(* Logix 5000 project; controller Test vendor 1 type 14 code 92 rev 33.11; software revision 33.00; part 2 of 2 *)
(* tags used below, declared in another part *)
   S15C : Banner_S15C_MGN_v4;
   Port_Data : Banner_IOL_Port_v4;
   Port : DINT;
   Local_Control : DINT;
   Command_Being_Processed : BOOL;
   Index_Write_Inprocess : INT;
   Index_Write_Control : INT;
   Update_Archive : BOOL;
   Inprocess_Index : DINT;
   RRS_Index2 : SINT;
   RRS_Index1 : SINT;
   RRS_Index3 : SINT;
   WRS_Index2 : SINT;
   WRS_Index3 : SINT;
   WRS_Index4 : SINT;
   WR_Control : DINT;
(* Banner_S15C_MGN_Param_v4, continued *)

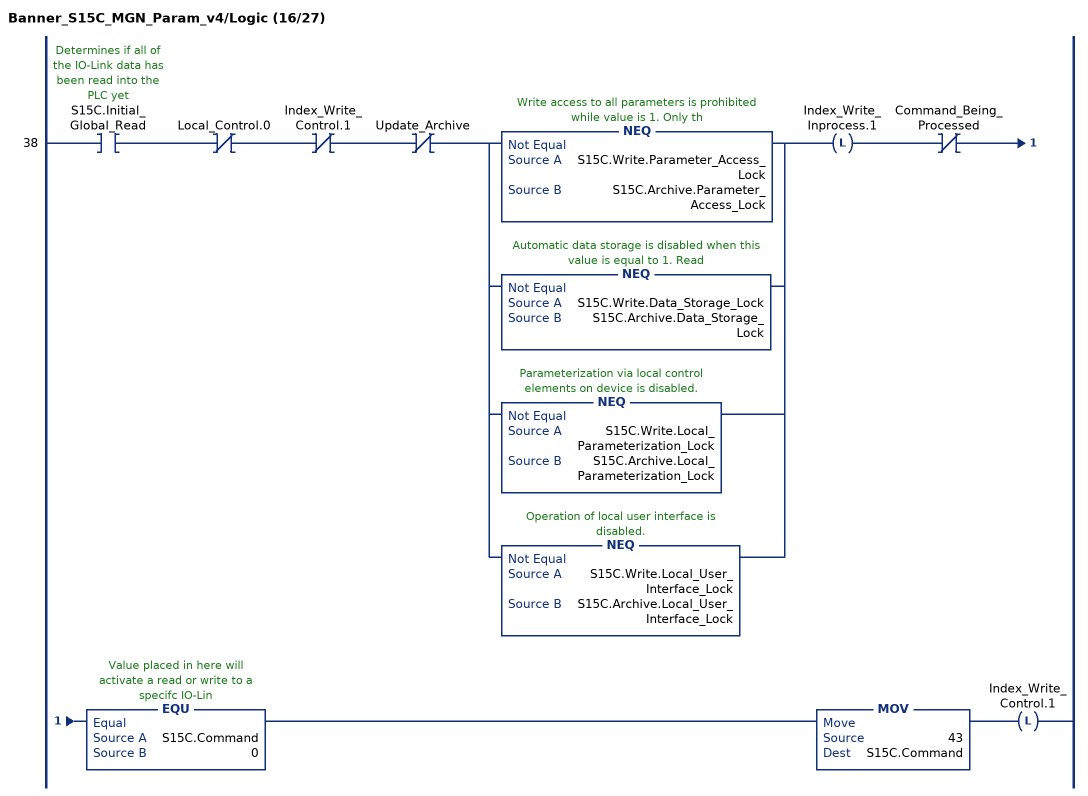
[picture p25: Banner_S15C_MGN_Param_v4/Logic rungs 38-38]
   38: XIC(S15C.Initial_Global_Read)XIO(Local_Control.0)XIO(Index_Write_Control.1)XIO(Update_Archive)[NEQ(S15C.Write.Parameter_Access_Lock,S15C.Archive.Parameter_Access_Lock) ,NEQ(S15C.Write.Data_Storage_Lock,S15C.Archive.Data_Storage_Lock) ,NEQ(S15C.Write.Local_Parameterization_Lock,S15C.Archive.Local_Parameterization_Lock) ,NEQ(S15C.Write.Local_User_Interface_Lock,S15C.Archive.Local_User_Interface_Lock) ]OTL(Index_Write_Inprocess.1)XIO(Command_Being_Processed)EQU(S15C.Command,0)MOV(43,S15C.Command)OTL(Index_Write_Control.1);
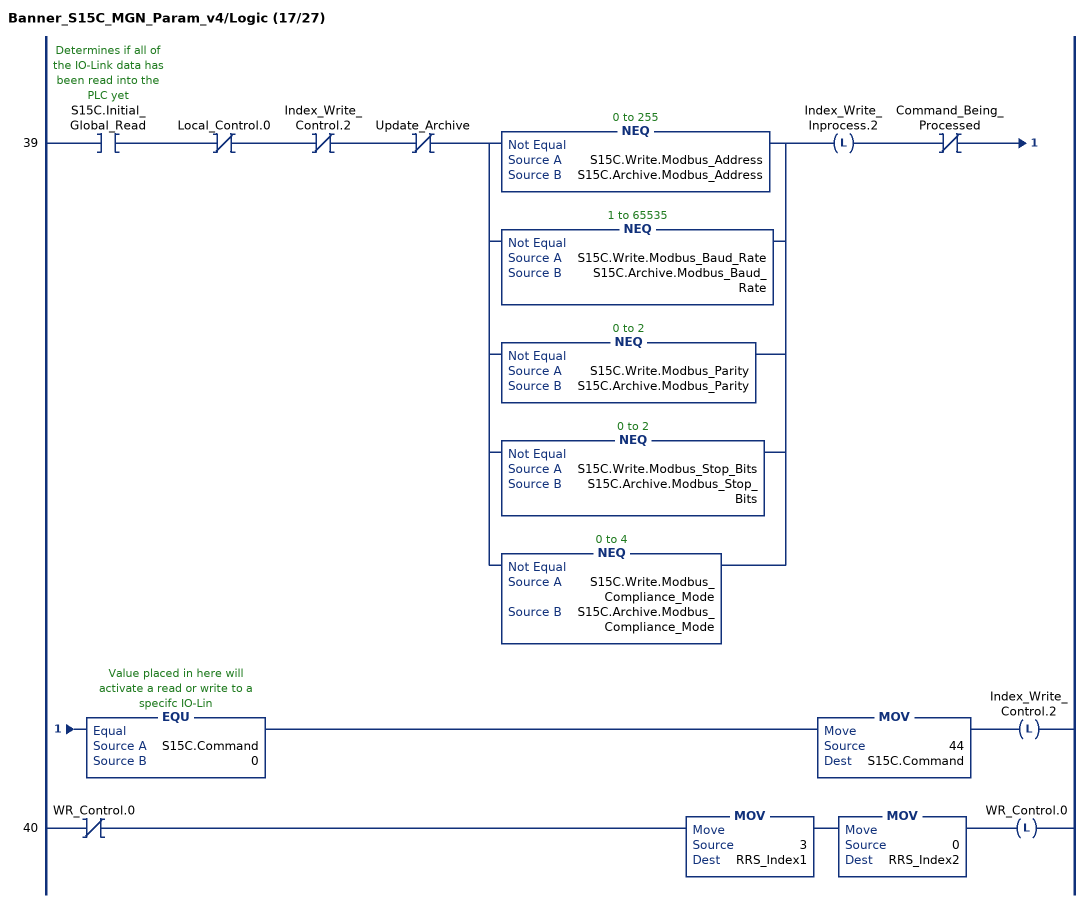
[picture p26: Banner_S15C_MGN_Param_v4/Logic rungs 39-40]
   39: XIC(S15C.Initial_Global_Read)XIO(Local_Control.0)XIO(Index_Write_Control.2)XIO(Update_Archive)[NEQ(S15C.Write.Modbus_Address,S15C.Archive.Modbus_Address) ,NEQ(S15C.Write.Modbus_Baud_Rate,S15C.Archive.Modbus_Baud_Rate) ,NEQ(S15C.Write.Modbus_Parity,S15C.Archive.Modbus_Parity) ,NEQ(S15C.Write.Modbus_Stop_Bits,S15C.Archive.Modbus_Stop_Bits) ,NEQ(S15C.Write.Modbus_Compliance_Mode,S15C.Archive.Modbus_Compliance_Mode) ]OTL(Index_Write_Inprocess.2)XIO(Command_Being_Processed)EQU(S15C.Command,0)MOV(44,S15C.Command)OTL(Index_Write_Control.2);
   40: XIO(WR_Control.0)MOV(3,RRS_Index1)MOV(0,RRS_Index2)OTL(WR_Control.0);
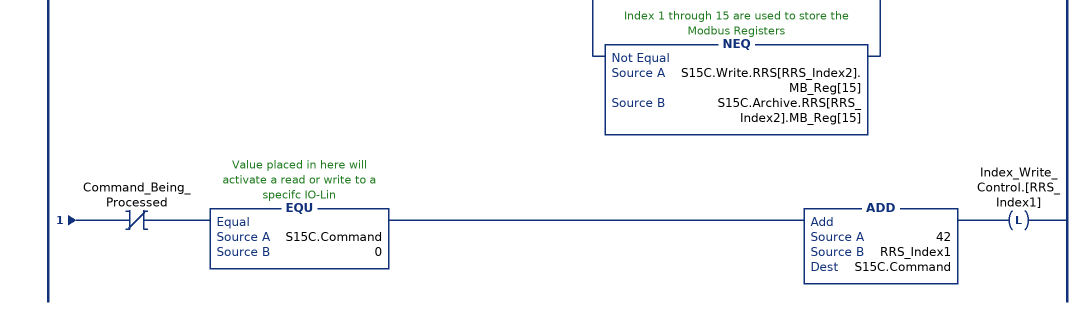
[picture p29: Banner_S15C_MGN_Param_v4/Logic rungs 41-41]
   41: XIC(S15C.Initial_Global_Read)XIC(WR_Control.0)XIO(Local_Control.0)XIO(Index_Write_Control.[RRS_Index1])XIO(Update_Archive)[NEQ(S15C.Write.RRS[RRS_Index2].MB_Reg[1],S15C.Archive.RRS[RRS_Index2].MB_Reg[1]) ,NEQ(S15C.Write.RRS[RRS_Index2].MB_Reg[2],S15C.Archive.RRS[RRS_Index2].MB_Reg[2]) ,NEQ(S15C.Write.RRS[RRS_Index2].MB_Reg[3],S15C.Archive.RRS[RRS_Index2].MB_Reg[3]) ,NEQ(S15C.Write.RRS[RRS_Index2].MB_Reg[4],S15C.Archive.RRS[RRS_Index2].MB_Reg[4]) ,NEQ(S15C.Write.RRS[RRS_Index2].MB_Reg[5],S15C.Archive.RRS[RRS_Index2].MB_Reg[5]) ,NEQ(S15C.Write.RRS[RRS_Index2].MB_Reg[6],S15C.Archive.RRS[RRS_Index2].MB_Reg[6]) ,NEQ(S15C.Write.RRS[RRS_Index2].MB_Reg[7],S15C.Archive.RRS[RRS_Index2].MB_Reg[7]) ,NEQ(S15C.Write.RRS[RRS_Index2].MB_Reg[8],S15C.Archive.RRS[RRS_Index2].MB_Reg[8]) ,NEQ(S15C.Write.RRS[RRS_Index2].MB_Reg[9],S15C.Archive.RRS[RRS_Index2].MB_Reg[9]) ,NEQ(S15C.Write.RRS[RRS_Index2].MB_Reg[10],S15C.Archive.RRS[RRS_Index2].MB_Reg[10]) ,NEQ(S15C.Write.RRS[RRS_Index2].MB_Reg[11],S15C.Archive.RRS[RRS_Index2].MB_Reg[11]) ,NEQ(S15C.Write.RRS[RRS_Index2].MB_Reg[12],S15C.Archive.RRS[RRS_Index2].MB_Reg[12]) ,NEQ(S15C.Write.RRS[RRS_Index2].MB_Reg[13],S15C.Archive.RRS[RRS_Index2].MB_Reg[13]) ,NEQ(S15C.Write.RRS[RRS_Index2].MB_Reg[14],S15C.Archive.RRS[RRS_Index2].MB_Reg[14]) ,NEQ(S15C.Write.RRS[RRS_Index2].MB_Reg[15],S15C.Archive.RRS[RRS_Index2].MB_Reg[15]) ]OTL(Index_Write_Inprocess.[RRS_Index1])XIO(Command_Being_Processed)EQU(S15C.Command,0)ADD(42,RRS_Index1,S15C.Command)OTL(Index_Write_Control.[RRS_Index1]);
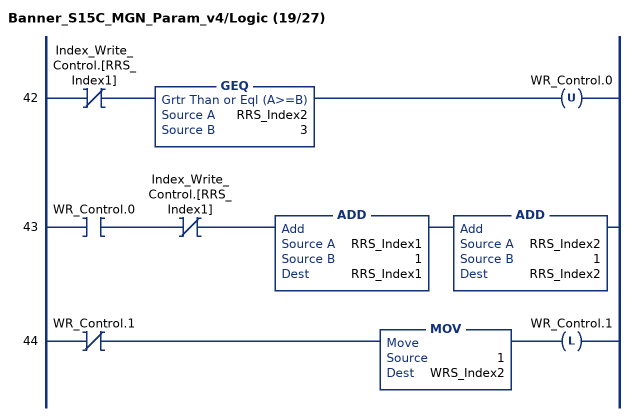
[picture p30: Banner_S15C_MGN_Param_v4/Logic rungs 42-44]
   42: XIO(Index_Write_Control.[RRS_Index1])GEQ(RRS_Index2,3)OTU(WR_Control.0);
   43: XIC(WR_Control.0)XIO(Index_Write_Control.[RRS_Index1])ADD(RRS_Index1,1,RRS_Index1)ADD(RRS_Index2,1,RRS_Index2);
   44: XIO(WR_Control.1)MOV(1,WRS_Index2)OTL(WR_Control.1);
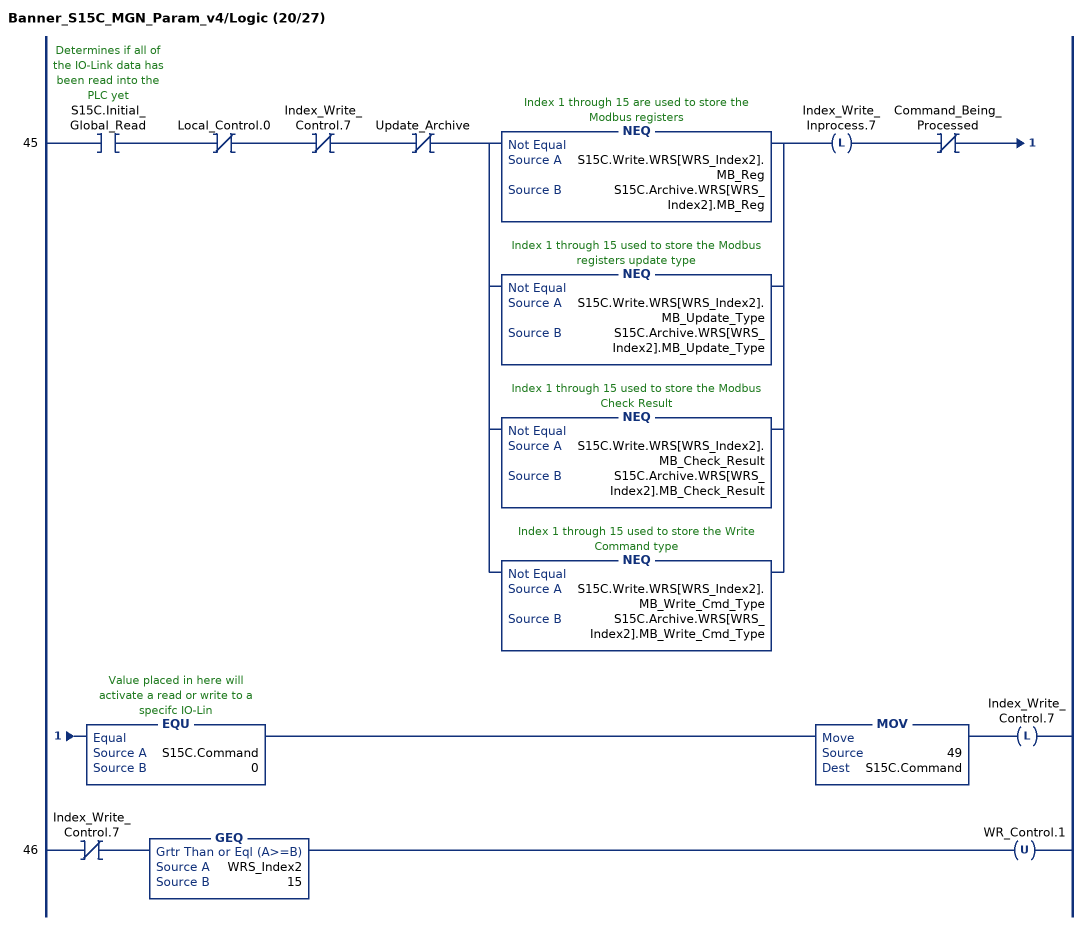
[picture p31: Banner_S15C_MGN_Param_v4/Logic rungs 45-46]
   45: XIC(S15C.Initial_Global_Read)XIO(Local_Control.0)XIO(Index_Write_Control.7)XIO(Update_Archive)[NEQ(S15C.Write.WRS[WRS_Index2].MB_Reg,S15C.Archive.WRS[WRS_Index2].MB_Reg) ,NEQ(S15C.Write.WRS[WRS_Index2].MB_Update_Type,S15C.Archive.WRS[WRS_Index2].MB_Update_Type) ,NEQ(S15C.Write.WRS[WRS_Index2].MB_Check_Result,S15C.Archive.WRS[WRS_Index2].MB_Check_Result) ,NEQ(S15C.Write.WRS[WRS_Index2].MB_Write_Cmd_Type,S15C.Archive.WRS[WRS_Index2].MB_Write_Cmd_Type) ]OTL(Index_Write_Inprocess.7)XIO(Command_Being_Processed)EQU(S15C.Command,0)MOV(49,S15C.Command)OTL(Index_Write_Control.7);
   46: XIO(Index_Write_Control.7)GEQ(WRS_Index2,15)OTU(WR_Control.1);
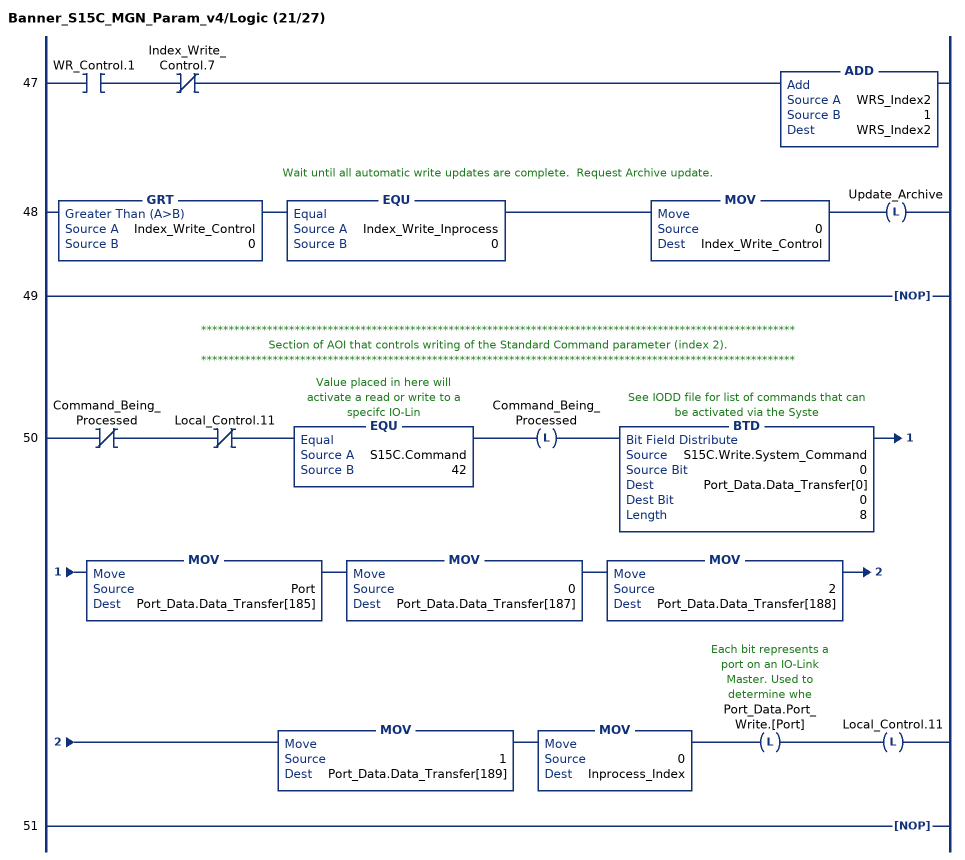
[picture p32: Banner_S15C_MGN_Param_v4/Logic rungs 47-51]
   47: XIC(WR_Control.1)XIO(Index_Write_Control.7)ADD(WRS_Index2,1,WRS_Index2);
   // Wait until all automatic write updates are complete.  Request Archive update.
   48: GRT(Index_Write_Control,0)EQU(Index_Write_Inprocess,0)MOV(0,Index_Write_Control)OTL(Update_Archive);
   49: NOP();
   // ************************************************************************************************************
   // Section of AOI that controls writing of the Standard Command parameter (index 2).
   // ************************************************************************************************************
   50: XIO(Command_Being_Processed)XIO(Local_Control.11)EQU(S15C.Command,42)OTL(Command_Being_Processed)BTD(S15C.Write.System_Command,0,Port_Data.Data_Transfer[0],0,8)MOV(Port,Port_Data.Data_Transfer[185])MOV(0,Port_Data.Data_Transfer[187])MOV(2,Port_Data.Data_Transfer[188])MOV(1,Port_Data.Data_Transfer[189])MOV(0,Inprocess_Index)OTL(Port_Data.Port_Write.[Port])OTL(Local_Control.11);
   51: NOP();
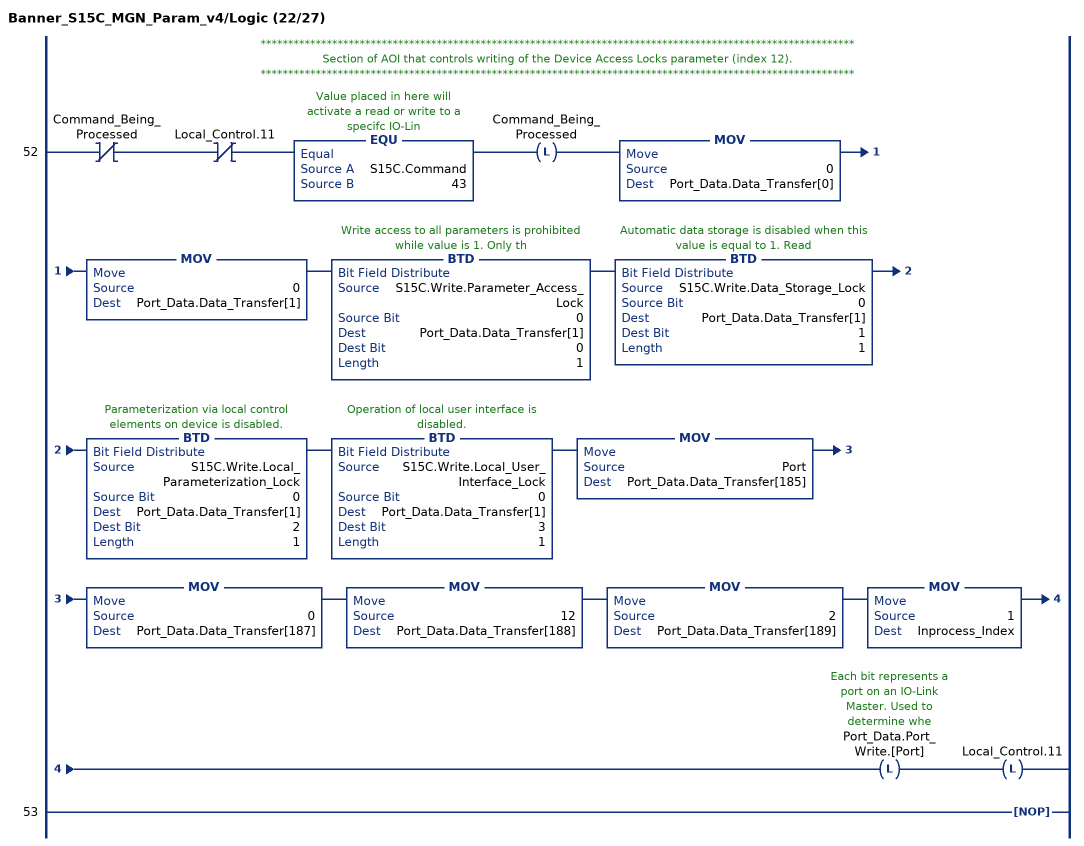
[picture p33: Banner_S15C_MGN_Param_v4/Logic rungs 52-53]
   // ************************************************************************************************************
   // Section of AOI that controls writing of the Device Access Locks parameter (index 12).
   // ************************************************************************************************************
   52: XIO(Command_Being_Processed)XIO(Local_Control.11)EQU(S15C.Command,43)OTL(Command_Being_Processed)MOV(0,Port_Data.Data_Transfer[0])MOV(0,Port_Data.Data_Transfer[1])BTD(S15C.Write.Parameter_Access_Lock,0,Port_Data.Data_Transfer[1],0,1)BTD(S15C.Write.Data_Storage_Lock,0,Port_Data.Data_Transfer[1],1,1)BTD(S15C.Write.Local_Parameterization_Lock,0,Port_Data.Data_Transfer[1],2,1)BTD(S15C.Write.Local_User_Interface_Lock,0,Port_Data.Data_Transfer[1],3,1)MOV(Port,Port_Data.Data_Transfer[185])MOV(0,Port_Data.Data_Transfer[187])MOV(12,Port_Data.Data_Transfer[188])MOV(2,Port_Data.Data_Transfer[189])MOV(1,Inprocess_Index)OTL(Port_Data.Port_Write.[Port])OTL(Local_Control.11);
   53: NOP();
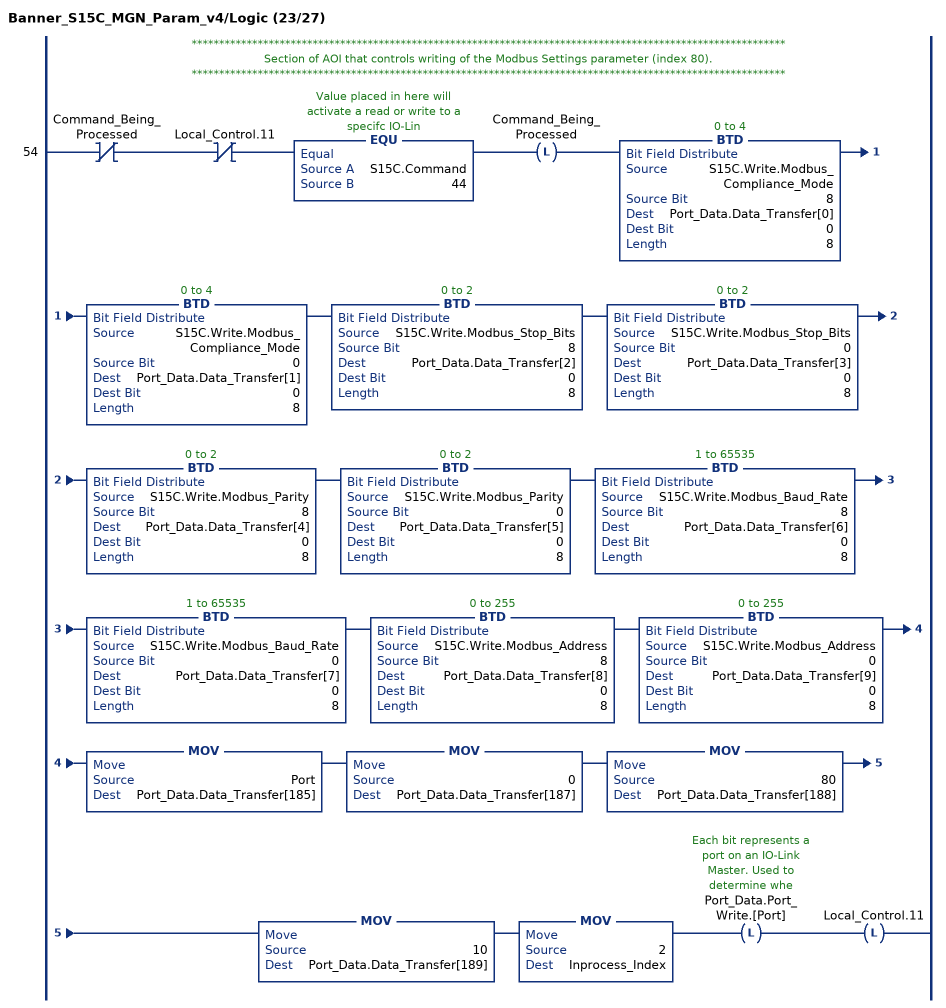
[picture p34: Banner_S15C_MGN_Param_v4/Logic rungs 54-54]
   // ************************************************************************************************************
   // Section of AOI that controls writing of the Modbus Settings parameter (index 80).
   // ************************************************************************************************************
   54: XIO(Command_Being_Processed)XIO(Local_Control.11)EQU(S15C.Command,44)OTL(Command_Being_Processed)BTD(S15C.Write.Modbus_Compliance_Mode,8,Port_Data.Data_Transfer[0],0,8)BTD(S15C.Write.Modbus_Compliance_Mode,0,Port_Data.Data_Transfer[1],0,8)BTD(S15C.Write.Modbus_Stop_Bits,8,Port_Data.Data_Transfer[2],0,8)BTD(S15C.Write.Modbus_Stop_Bits,0,Port_Data.Data_Transfer[3],0,8)BTD(S15C.Write.Modbus_Parity,8,Port_Data.Data_Transfer[4],0,8)BTD(S15C.Write.Modbus_Parity,0,Port_Data.Data_Transfer[5],0,8)BTD(S15C.Write.Modbus_Baud_Rate,8,Port_Data.Data_Transfer[6],0,8)BTD(S15C.Write.Modbus_Baud_Rate,0,Port_Data.Data_Transfer[7],0,8)BTD(S15C.Write.Modbus_Address,8,Port_Data.Data_Transfer[8],0,8)BTD(S15C.Write.Modbus_Address,0,Port_Data.Data_Transfer[9],0,8)MOV(Port,Port_Data.Data_Transfer[185])MOV(0,Port_Data.Data_Transfer[187])MOV(80,Port_Data.Data_Transfer[188])MOV(10,Port_Data.Data_Transfer[189])MOV(2,Inprocess_Index)OTL(Port_Data.Port_Write.[Port])OTL(Local_Control.11);
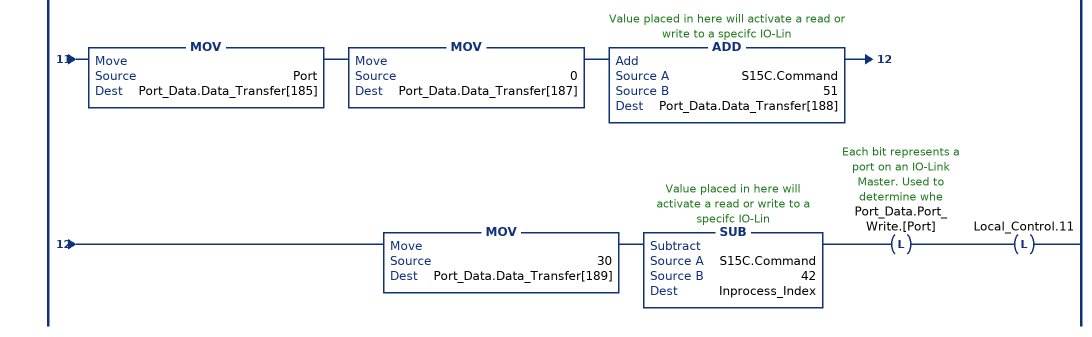
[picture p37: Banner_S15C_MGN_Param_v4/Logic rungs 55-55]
   // ************************************************************************************************************
   // Section of AOI that controls writing of the Read Registers Set 0 through 3 Settings parameter (index 96 to 99).
   // ************************************************************************************************************
   55: XIO(Command_Being_Processed)XIO(Local_Control.11)GEQ(S15C.Command,45)LEQ(S15C.Command,48)SUB(S15C.Command,45,RRS_Index3)OTL(Command_Being_Processed)BTD(S15C.Write.RRS[RRS_Index3].MB_Reg[15],8,Port_Data.Data_Transfer[0],0,8)BTD(S15C.Write.RRS[RRS_Index3].MB_Reg[15],0,Port_Data.Data_Transfer[1],0,8)BTD(S15C.Write.RRS[RRS_Index3].MB_Reg[14],8,Port_Data.Data_Transfer[2],0,8)BTD(S15C.Write.RRS[RRS_Index3].MB_Reg[14],0,Port_Data.Data_Transfer[3],0,8)BTD(S15C.Write.RRS[RRS_Index3].MB_Reg[13],8,Port_Data.Data_Transfer[4],0,8)BTD(S15C.Write.RRS[RRS_Index3].MB_Reg[13],0,Port_Data.Data_Transfer[5],0,8)BTD(S15C.Write.RRS[RRS_Index3].MB_Reg[12],8,Port_Data.Data_Transfer[6],0,8)BTD(S15C.Write.RRS[RRS_Index3].MB_Reg[12],0,Port_Data.Data_Transfer[7],0,8)BTD(S15C.Write.RRS[RRS_Index3].MB_Reg[11],8,Port_Data.Data_Transfer[8],0,8)BTD(S15C.Write.RRS[RRS_Index3].MB_Reg[11],0,Port_Data.Data_Transfer[9],0,8)BTD(S15C.Write.RRS[RRS_Index3].MB_Reg[10],8,Port_Data.Data_Transfer[10],0,8)BTD(S15C.Write.RRS[RRS_Index3].MB_Reg[10],0,Port_Data.Data_Transfer[11],0,8)BTD(S15C.Write.RRS[RRS_Index3].MB_Reg[9],8,Port_Data.Data_Transfer[12],0,8)BTD(S15C.Write.RRS[RRS_Index3].MB_Reg[9],0,Port_Data.Data_Transfer[13],0,8)BTD(S15C.Write.RRS[RRS_Index3].MB_Reg[8],8,Port_Data.Data_Transfer[14],0,8)BTD(S15C.Write.RRS[RRS_Index3].MB_Reg[8],0,Port_Data.Data_Transfer[15],0,8)BTD(S15C.Write.RRS[RRS_Index3].MB_Reg[7],8,Port_Data.Data_Transfer[16],0,8)BTD(S15C.Write.RRS[RRS_Index3].MB_Reg[7],0,Port_Data.Data_Transfer[17],0,8)BTD(S15C.Write.RRS[RRS_Index3].MB_Reg[6],8,Port_Data.Data_Transfer[18],0,8)BTD(S15C.Write.RRS[RRS_Index3].MB_Reg[6],0,Port_Data.Data_Transfer[19],0,8)BTD(S15C.Write.RRS[RRS_Index3].MB_Reg[5],8,Port_Data.Data_Transfer[20],0,8)BTD(S15C.Write.RRS[RRS_Index3].MB_Reg[5],0,Port_Data.Data_Transfer[21],0,8)BTD(S15C.Write.RRS[RRS_Index3].MB_Reg[4],8,Port_Data.Data_Transfer[22],0,8)BTD(S15C.Write.RRS[RRS_Index3].MB_Reg[4],0,Port_Data.Data_Transfer[23],0,8)BTD(S15C.Write.RRS[RRS_Index3].MB_Reg[3],8,Port_Data.Data_Transfer[24],0,8)BTD(S15C.Write.RRS[RRS_Index3].MB_Reg[3],0,Port_Data.Data_Transfer[25],0,8)BTD(S15C.Write.RRS[RRS_Index3].MB_Reg[2],8,Port_Data.Data_Transfer[26],0,8)BTD(S15C.Write.RRS[RRS_Index3].MB_Reg[2],0,Port_Data.Data_Transfer[27],0,8)BTD(S15C.Write.RRS[RRS_Index3].MB_Reg[1],8,Port_Data.Data_Transfer[28],0,8)BTD(S15C.Write.RRS[RRS_Index3].MB_Reg[1],0,Port_Data.Data_Transfer[29],0,8)MOV(Port,Port_Data.Data_Transfer[185])MOV(0,Port_Data.Data_Transfer[187])ADD(S15C.Command,51,Port_Data.Data_Transfer[188])MOV(30,Port_Data.Data_Transfer[189])SUB(S15C.Command,42,Inprocess_Index)OTL(Port_Data.Port_Write.[Port])OTL(Local_Control.11);
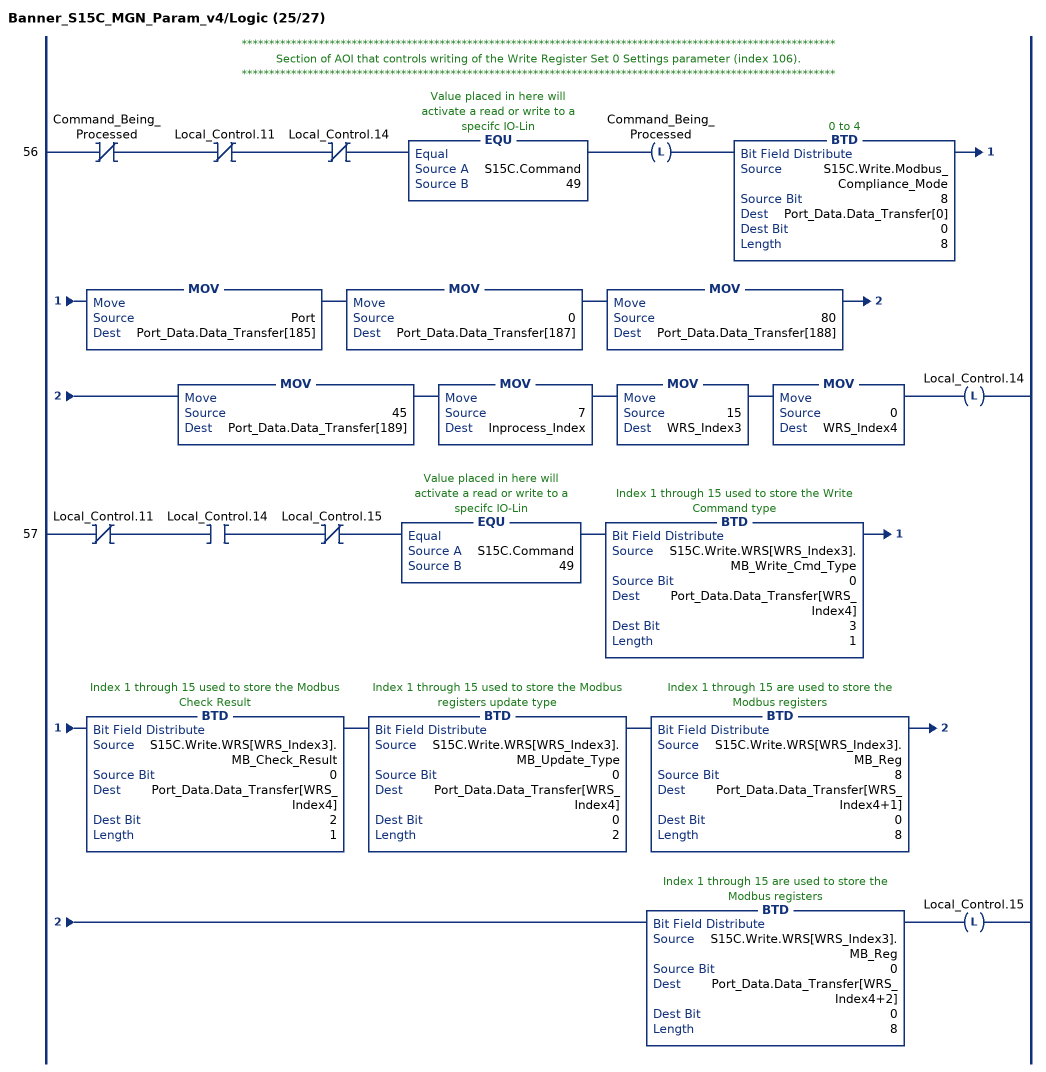
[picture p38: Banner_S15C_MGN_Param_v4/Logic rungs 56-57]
   // ************************************************************************************************************
   // Section of AOI that controls writing of the Write Register Set 0 Settings parameter (index 106).
   // ************************************************************************************************************
   56: XIO(Command_Being_Processed)XIO(Local_Control.11)XIO(Local_Control.14)EQU(S15C.Command,49)OTL(Command_Being_Processed)BTD(S15C.Write.Modbus_Compliance_Mode,8,Port_Data.Data_Transfer[0],0,8)MOV(Port,Port_Data.Data_Transfer[185])MOV(0,Port_Data.Data_Transfer[187])MOV(80,Port_Data.Data_Transfer[188])MOV(45,Port_Data.Data_Transfer[189])MOV(7,Inprocess_Index)MOV(15,WRS_Index3)MOV(0,WRS_Index4)OTL(Local_Control.14);
   57: XIO(Local_Control.11)XIC(Local_Control.14)XIO(Local_Control.15)EQU(S15C.Command,49)BTD(S15C.Write.WRS[WRS_Index3].MB_Write_Cmd_Type,0,Port_Data.Data_Transfer[WRS_Index4],3,1)BTD(S15C.Write.WRS[WRS_Index3].MB_Check_Result,0,Port_Data.Data_Transfer[WRS_Index4],2,1)BTD(S15C.Write.WRS[WRS_Index3].MB_Update_Type,0,Port_Data.Data_Transfer[WRS_Index4],0,2)BTD(S15C.Write.WRS[WRS_Index3].MB_Reg,8,Port_Data.Data_Transfer[WRS_Index4+1],0,8)BTD(S15C.Write.WRS[WRS_Index3].MB_Reg,0,Port_Data.Data_Transfer[WRS_Index4+2],0,8)OTL(Local_Control.15);
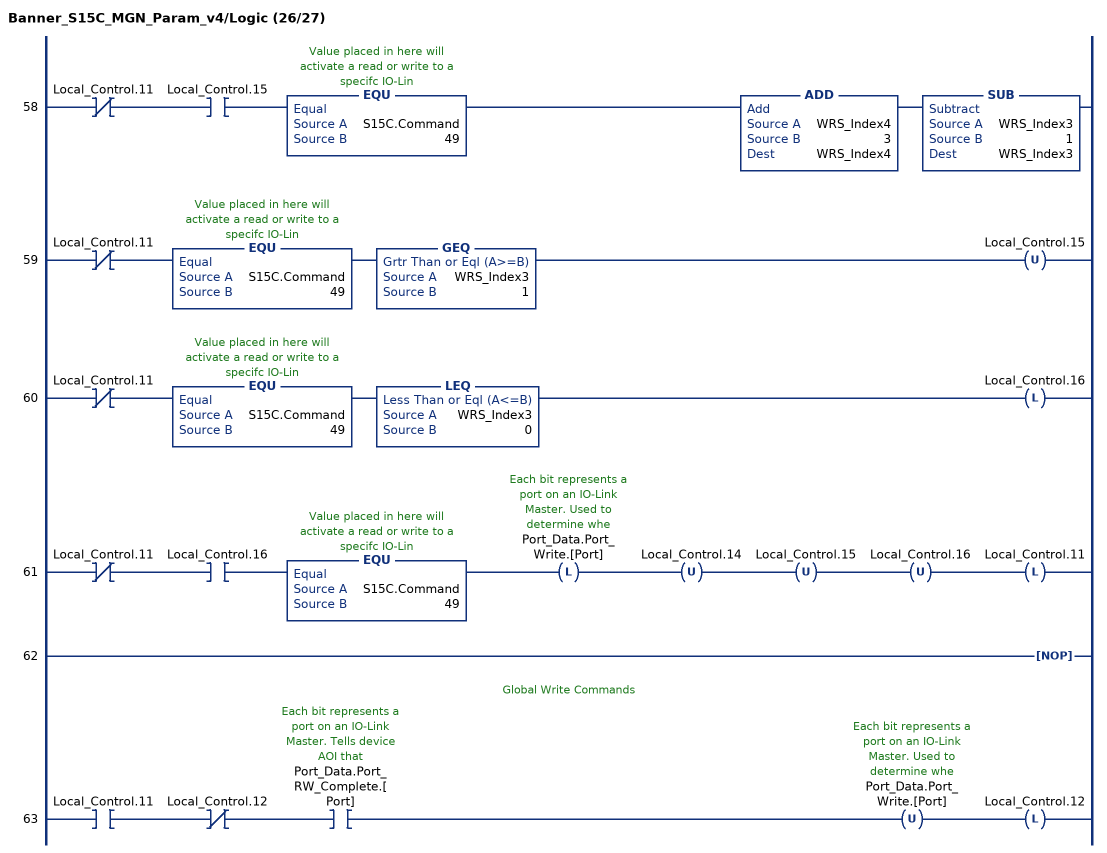
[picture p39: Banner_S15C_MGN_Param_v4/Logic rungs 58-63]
   58: XIO(Local_Control.11)XIC(Local_Control.15)EQU(S15C.Command,49)ADD(WRS_Index4,3,WRS_Index4)SUB(WRS_Index3,1,WRS_Index3);
   59: XIO(Local_Control.11)EQU(S15C.Command,49)GEQ(WRS_Index3,1)OTU(Local_Control.15);
   60: XIO(Local_Control.11)EQU(S15C.Command,49)LEQ(WRS_Index3,0)OTL(Local_Control.16);
   61: XIO(Local_Control.11)XIC(Local_Control.16)EQU(S15C.Command,49)OTL(Port_Data.Port_Write.[Port])OTU(Local_Control.14)OTU(Local_Control.15)OTU(Local_Control.16)OTL(Local_Control.11);
   62: NOP();
   // Global Write Commands
   63: XIC(Local_Control.11)XIO(Local_Control.12)XIC(Port_Data.Port_RW_Complete.[Port])OTU(Port_Data.Port_Write.[Port])OTL(Local_Control.12);
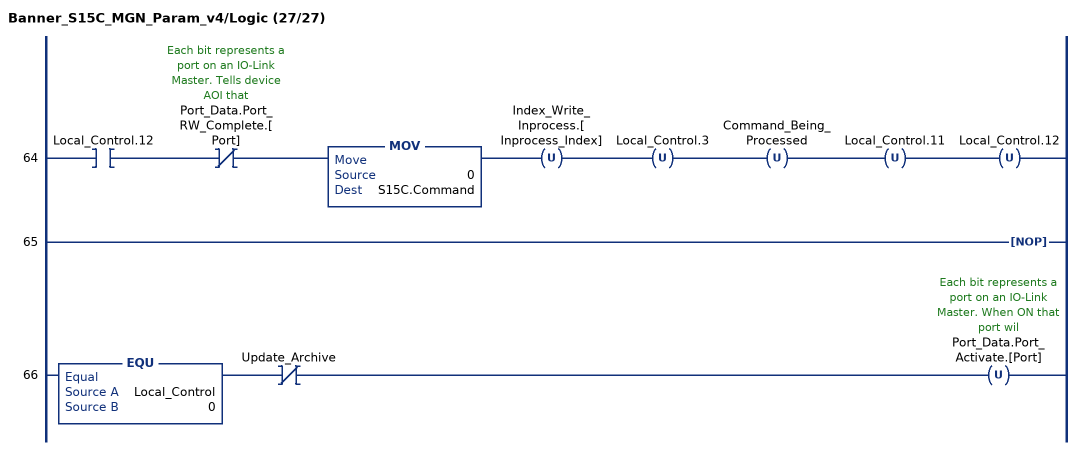
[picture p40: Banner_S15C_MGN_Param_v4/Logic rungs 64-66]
   64: XIC(Local_Control.12)XIO(Port_Data.Port_RW_Complete.[Port])MOV(0,S15C.Command)OTU(Index_Write_Inprocess.[Inprocess_Index])OTU(Local_Control.3)OTU(Command_Being_Processed)OTU(Local_Control.11)OTU(Local_Control.12);
   65: NOP();
   66: EQU(Local_Control,0)XIO(Update_Archive)OTU(Port_Data.Port_Activate.[Port]);
END_ROUTINE
END_ADD_ON_INSTRUCTION

ADD_ON_INSTRUCTION Banner_S15C_MGN_PD_v4   (* revision 4.0, vendor Banner Engineering *)
// AOI that used with the S15C MGN sensor.
VAR_IN_OUT
   PD : Banner_S15C_MGN_PDIO_v4; {required}
END_VAR
VAR_INPUT
   Byte_Swap : BOOL; {required}
END_VAR
VAR
   TempR : SINT[32]; {access None}
   W_Index : SINT; {access None}
   DTI_Index : SINT; {access None}
   R_Index : SINT; {access None}
   DTO_Index : SINT; {access None}
   R_Data_Update : BOOL; {access None}
   TempW : SINT[32]; {access None}
   W_Data_Update : BOOL; {access None}
END_VAR

ROUTINE Logic   (* ladder *)
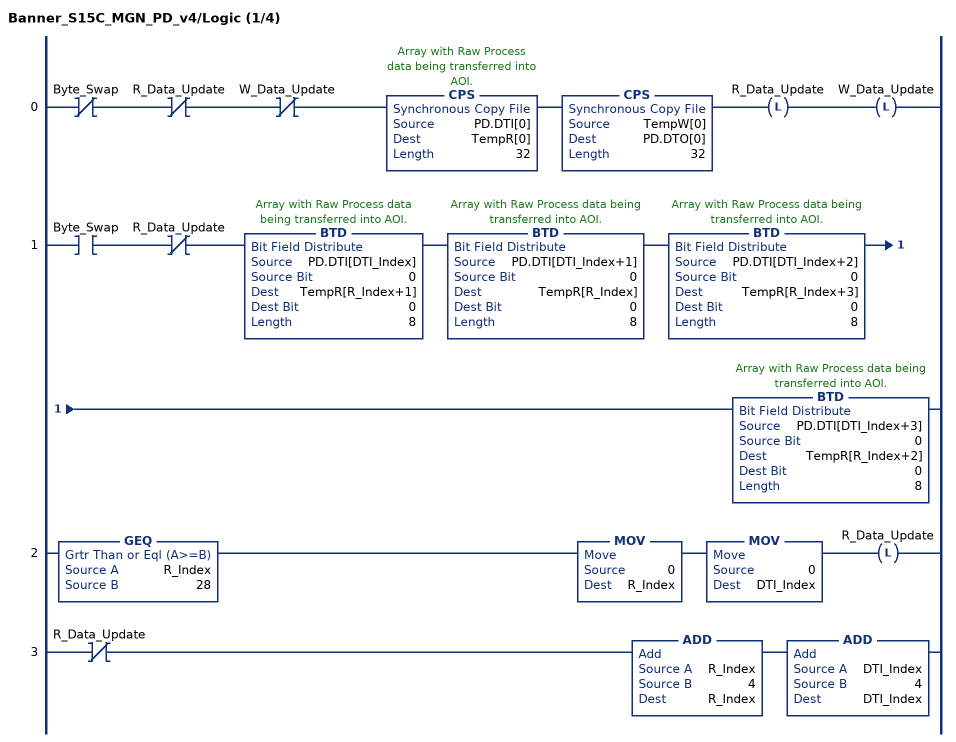
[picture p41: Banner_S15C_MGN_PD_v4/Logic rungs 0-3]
   0: XIO(Byte_Swap)XIO(R_Data_Update)XIO(W_Data_Update)CPS(PD.DTI[0],TempR[0],32)CPS(TempW[0],PD.DTO[0],32)OTL(R_Data_Update)OTL(W_Data_Update);
   1: XIC(Byte_Swap)XIO(R_Data_Update)BTD(PD.DTI[DTI_Index],0,TempR[R_Index+1],0,8)BTD(PD.DTI[DTI_Index+1],0,TempR[R_Index],0,8)BTD(PD.DTI[DTI_Index+2],0,TempR[R_Index+3],0,8)BTD(PD.DTI[DTI_Index+3],0,TempR[R_Index+2],0,8);
   2: GEQ(R_Index,28)MOV(0,R_Index)MOV(0,DTI_Index)OTL(R_Data_Update);
   3: XIO(R_Data_Update)ADD(R_Index,4,R_Index)ADD(DTI_Index,4,DTI_Index);
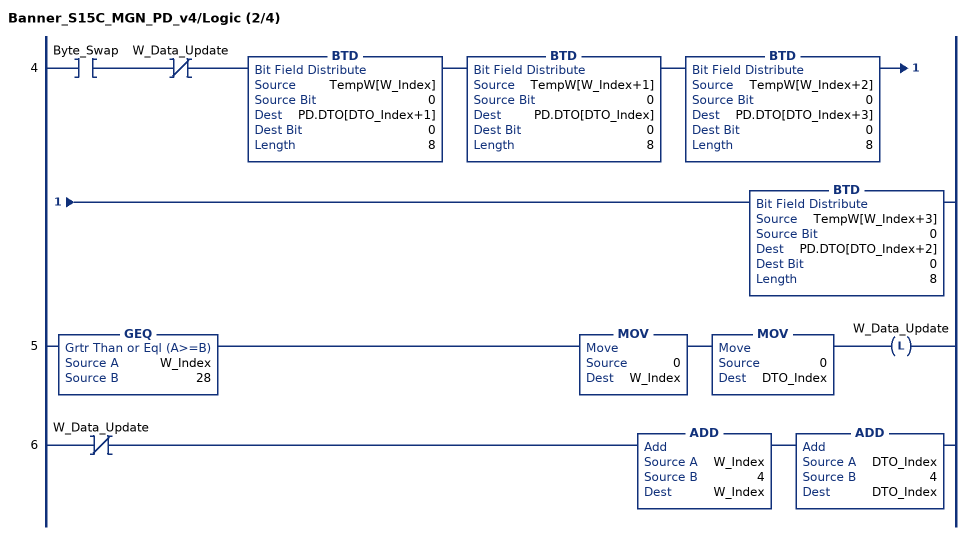
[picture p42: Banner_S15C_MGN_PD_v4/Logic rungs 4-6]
   4: XIC(Byte_Swap)XIO(W_Data_Update)BTD(TempW[W_Index],0,PD.DTO[DTO_Index+1],0,8)BTD(TempW[W_Index+1],0,PD.DTO[DTO_Index],0,8)BTD(TempW[W_Index+2],0,PD.DTO[DTO_Index+3],0,8)BTD(TempW[W_Index+3],0,PD.DTO[DTO_Index+2],0,8);
   5: GEQ(W_Index,28)MOV(0,W_Index)MOV(0,DTO_Index)OTL(W_Data_Update);
   6: XIO(W_Data_Update)ADD(W_Index,4,W_Index)ADD(DTO_Index,4,DTO_Index);
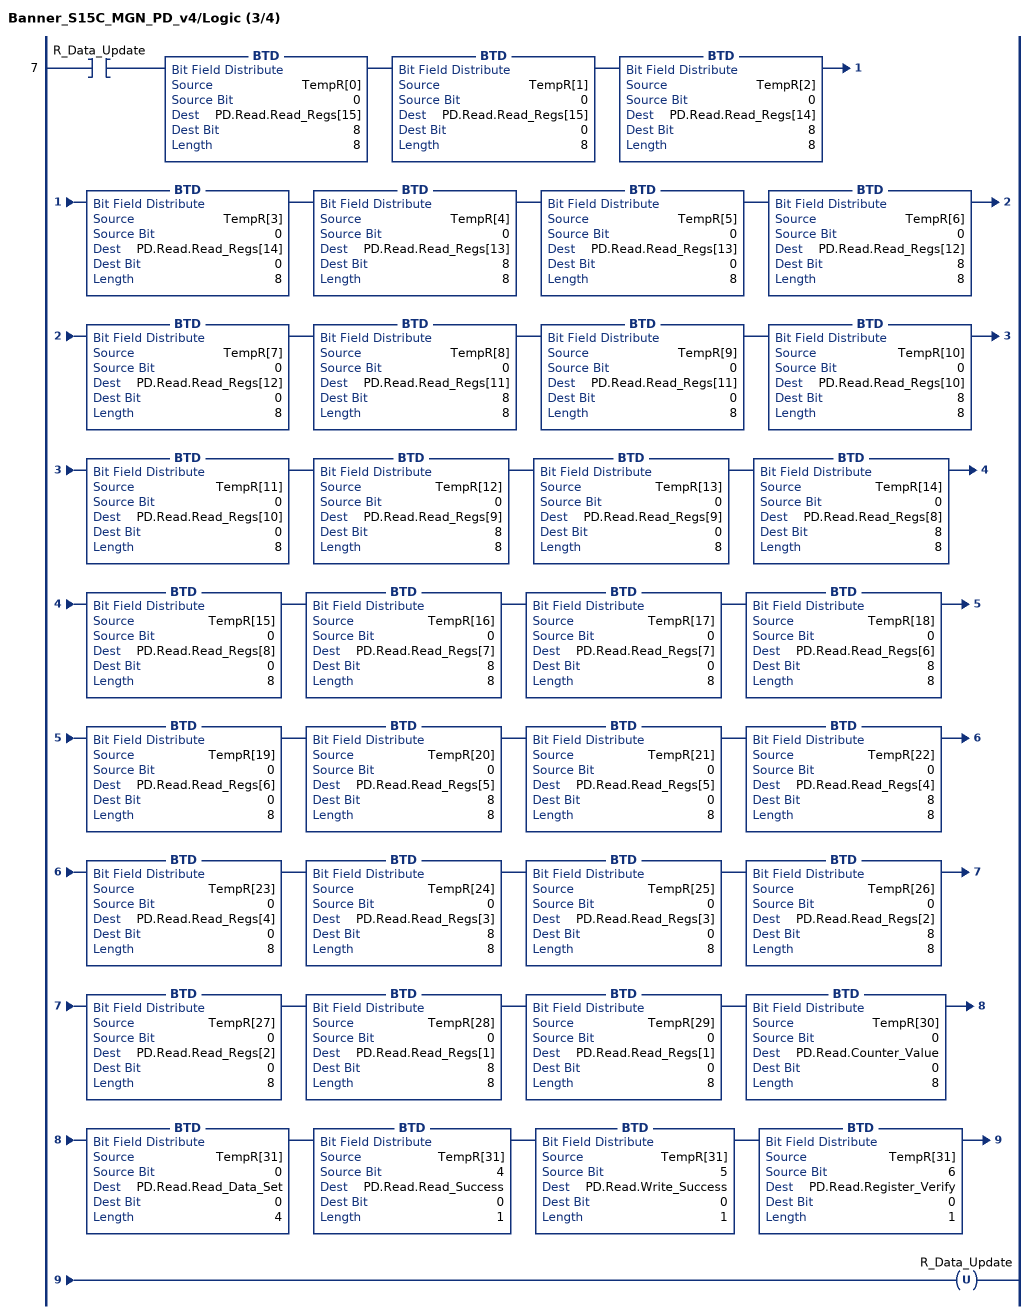
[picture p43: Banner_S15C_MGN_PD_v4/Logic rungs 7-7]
   7: XIC(R_Data_Update)BTD(TempR[0],0,PD.Read.Read_Regs[15],8,8)BTD(TempR[1],0,PD.Read.Read_Regs[15],0,8)BTD(TempR[2],0,PD.Read.Read_Regs[14],8,8)BTD(TempR[3],0,PD.Read.Read_Regs[14],0,8)BTD(TempR[4],0,PD.Read.Read_Regs[13],8,8)BTD(TempR[5],0,PD.Read.Read_Regs[13],0,8)BTD(TempR[6],0,PD.Read.Read_Regs[12],8,8)BTD(TempR[7],0,PD.Read.Read_Regs[12],0,8)BTD(TempR[8],0,PD.Read.Read_Regs[11],8,8)BTD(TempR[9],0,PD.Read.Read_Regs[11],0,8)BTD(TempR[10],0,PD.Read.Read_Regs[10],8,8)BTD(TempR[11],0,PD.Read.Read_Regs[10],0,8)BTD(TempR[12],0,PD.Read.Read_Regs[9],8,8)BTD(TempR[13],0,PD.Read.Read_Regs[9],0,8)BTD(TempR[14],0,PD.Read.Read_Regs[8],8,8)BTD(TempR[15],0,PD.Read.Read_Regs[8],0,8)BTD(TempR[16],0,PD.Read.Read_Regs[7],8,8)BTD(TempR[17],0,PD.Read.Read_Regs[7],0,8)BTD(TempR[18],0,PD.Read.Read_Regs[6],8,8)BTD(TempR[19],0,PD.Read.Read_Regs[6],0,8)BTD(TempR[20],0,PD.Read.Read_Regs[5],8,8)BTD(TempR[21],0,PD.Read.Read_Regs[5],0,8)BTD(TempR[22],0,PD.Read.Read_Regs[4],8,8)BTD(TempR[23],0,PD.Read.Read_Regs[4],0,8)BTD(TempR[24],0,PD.Read.Read_Regs[3],8,8)BTD(TempR[25],0,PD.Read.Read_Regs[3],0,8)BTD(TempR[26],0,PD.Read.Read_Regs[2],8,8)BTD(TempR[27],0,PD.Read.Read_Regs[2],0,8)BTD(TempR[28],0,PD.Read.Read_Regs[1],8,8)BTD(TempR[29],0,PD.Read.Read_Regs[1],0,8)BTD(TempR[30],0,PD.Read.Counter_Value,0,8)BTD(TempR[31],0,PD.Read.Read_Data_Set,0,4)BTD(TempR[31],4,PD.Read.Read_Success,0,1)BTD(TempR[31],5,PD.Read.Write_Success,0,1)BTD(TempR[31],6,PD.Read.Register_Verify,0,1)OTU(R_Data_Update);
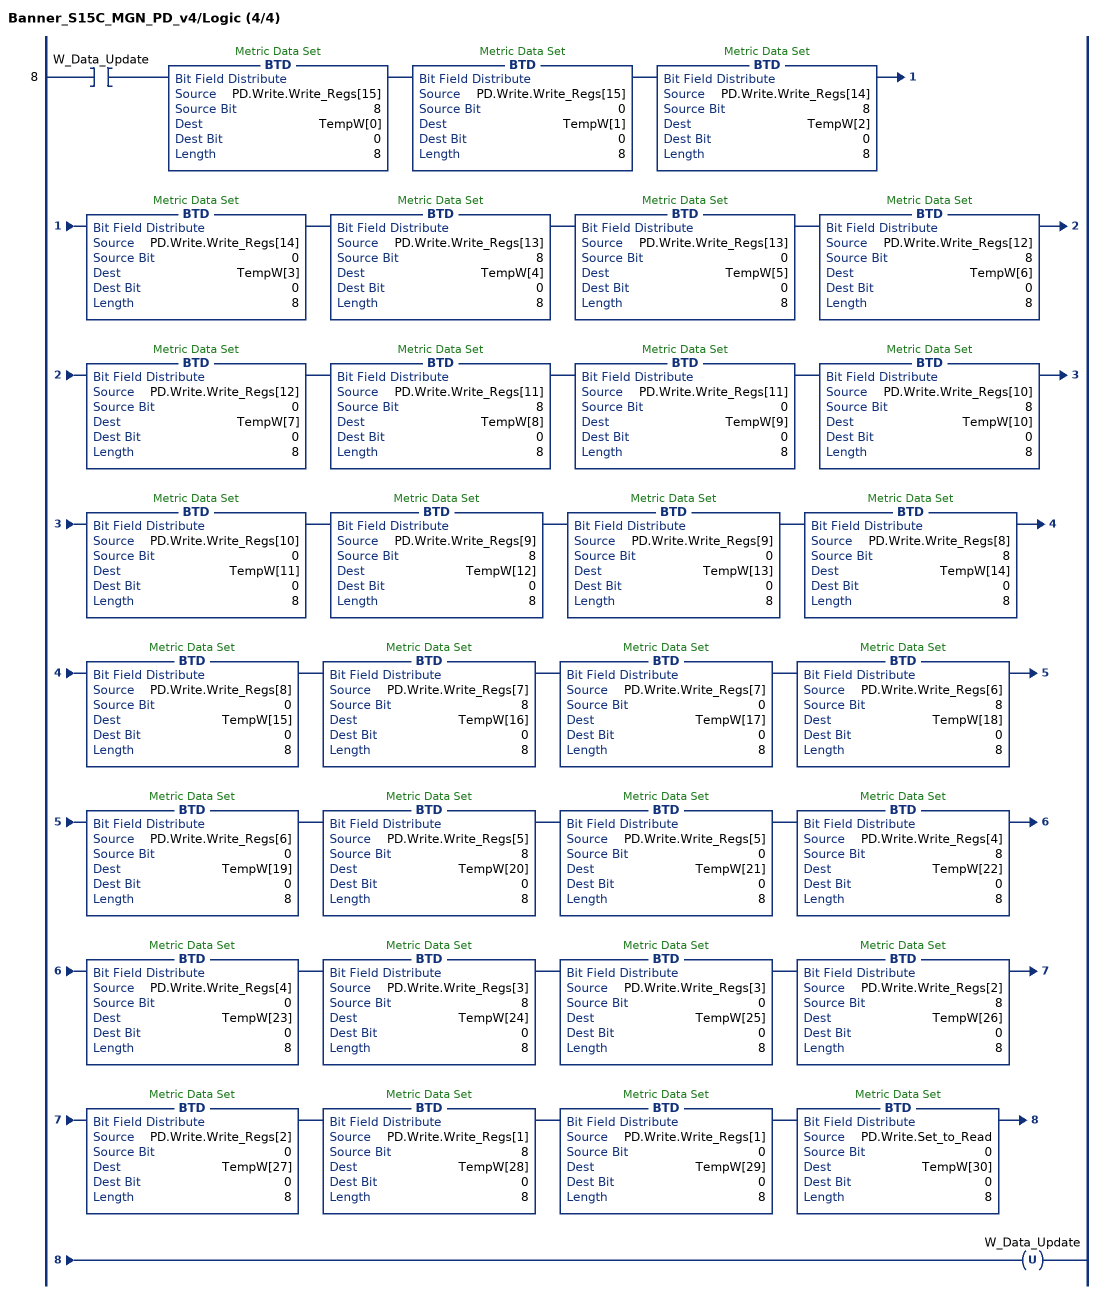
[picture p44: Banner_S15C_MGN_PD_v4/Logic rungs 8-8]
   8: XIC(W_Data_Update)BTD(PD.Write.Write_Regs[15],8,TempW[0],0,8)BTD(PD.Write.Write_Regs[15],0,TempW[1],0,8)BTD(PD.Write.Write_Regs[14],8,TempW[2],0,8)BTD(PD.Write.Write_Regs[14],0,TempW[3],0,8)BTD(PD.Write.Write_Regs[13],8,TempW[4],0,8)BTD(PD.Write.Write_Regs[13],0,TempW[5],0,8)BTD(PD.Write.Write_Regs[12],8,TempW[6],0,8)BTD(PD.Write.Write_Regs[12],0,TempW[7],0,8)BTD(PD.Write.Write_Regs[11],8,TempW[8],0,8)BTD(PD.Write.Write_Regs[11],0,TempW[9],0,8)BTD(PD.Write.Write_Regs[10],8,TempW[10],0,8)BTD(PD.Write.Write_Regs[10],0,TempW[11],0,8)BTD(PD.Write.Write_Regs[9],8,TempW[12],0,8)BTD(PD.Write.Write_Regs[9],0,TempW[13],0,8)BTD(PD.Write.Write_Regs[8],8,TempW[14],0,8)BTD(PD.Write.Write_Regs[8],0,TempW[15],0,8)BTD(PD.Write.Write_Regs[7],8,TempW[16],0,8)BTD(PD.Write.Write_Regs[7],0,TempW[17],0,8)BTD(PD.Write.Write_Regs[6],8,TempW[18],0,8)BTD(PD.Write.Write_Regs[6],0,TempW[19],0,8)BTD(PD.Write.Write_Regs[5],8,TempW[20],0,8)BTD(PD.Write.Write_Regs[5],0,TempW[21],0,8)BTD(PD.Write.Write_Regs[4],8,TempW[22],0,8)BTD(PD.Write.Write_Regs[4],0,TempW[23],0,8)BTD(PD.Write.Write_Regs[3],8,TempW[24],0,8)BTD(PD.Write.Write_Regs[3],0,TempW[25],0,8)BTD(PD.Write.Write_Regs[2],8,TempW[26],0,8)BTD(PD.Write.Write_Regs[2],0,TempW[27],0,8)BTD(PD.Write.Write_Regs[1],8,TempW[28],0,8)BTD(PD.Write.Write_Regs[1],0,TempW[29],0,8)BTD(PD.Write.Set_to_Read,0,TempW[30],0,8)OTU(W_Data_Update);
END_ROUTINE
END_ADD_ON_INSTRUCTION

VAR_GLOBAL   (* controller tags *)
   IOLM1 : Banner_IOLM_v4;
   IOLM1_Status : Banner_DXMR90_IOLM_v4;
   Reset : BOOL;
   S15C_IOLM1_01 : Banner_S15C_MGN_v4;
   S15C_IOLM1_01_PD : Banner_S15C_MGN_PDIO_v4 := (Read.Read_Regs[1] := 4640, Read.Read_Regs[2] := 484, Read.Read_Regs[3] := 1512);
   S15C_IOLM1_01_PD_Status : Banner_S15C_MGN_PD_v4;
   S15C_IOLM1_01_Status : Banner_S15C_MGN_Param_v4;
END_VAR

PROGRAM MainProgram   (* main routine MainRoutine *)

ROUTINE MainRoutine   (* ladder *)
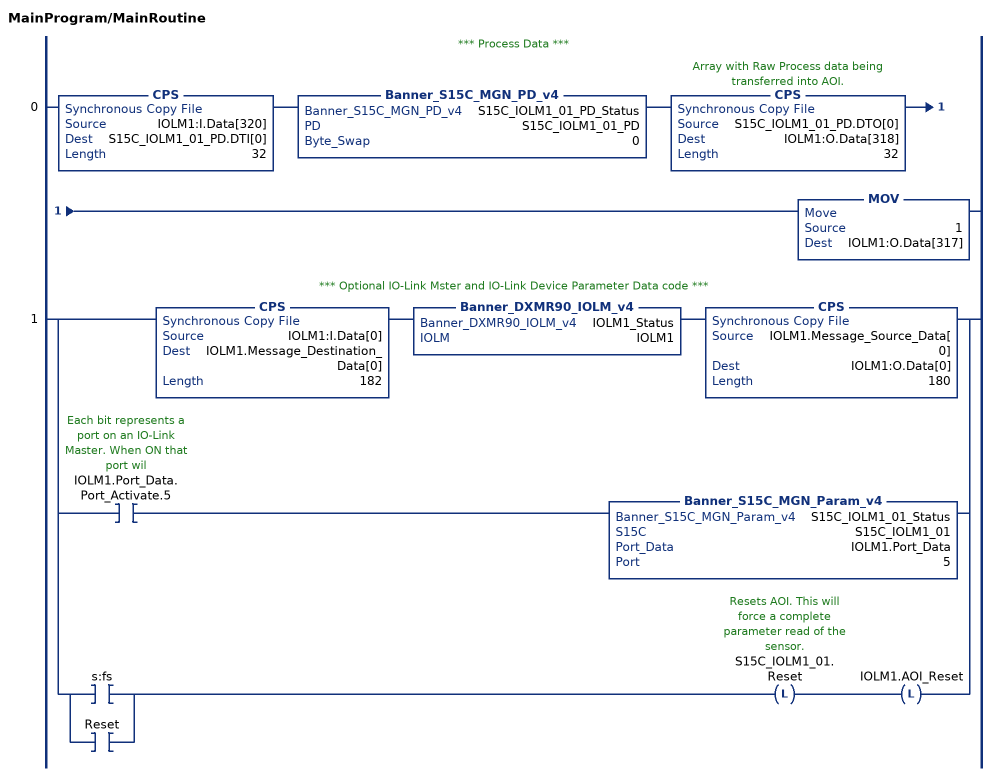
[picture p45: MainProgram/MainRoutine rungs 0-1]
   // *** Process Data ***
   0: CPS(IOLM1:I.Data[320],S15C_IOLM1_01_PD.DTI[0],32)Banner_S15C_MGN_PD_v4(S15C_IOLM1_01_PD_Status,S15C_IOLM1_01_PD,0)CPS(S15C_IOLM1_01_PD.DTO[0],IOLM1:O.Data[318],32)MOV(1,IOLM1:O.Data[317]);
   // *** Optional IO-Link Mster and IO-Link Device Parameter Data code ***
   1: [CPS(IOLM1:I.Data[0],IOLM1.Message_Destination_Data[0],182) Banner_DXMR90_IOLM_v4(IOLM1_Status,IOLM1) CPS(IOLM1.Message_Source_Data[0],IOLM1:O.Data[0],180) ,XIC(IOLM1.Port_Data.Port_Activate.5) Banner_S15C_MGN_Param_v4(S15C_IOLM1_01_Status,S15C_IOLM1_01,IOLM1.Port_Data,5) ,[XIC(s:fs) ,XIC(Reset) ] OTL(S15C_IOLM1_01.Reset) OTL(IOLM1.AOI_Reset) ];
END_ROUTINE
END_PROGRAM
